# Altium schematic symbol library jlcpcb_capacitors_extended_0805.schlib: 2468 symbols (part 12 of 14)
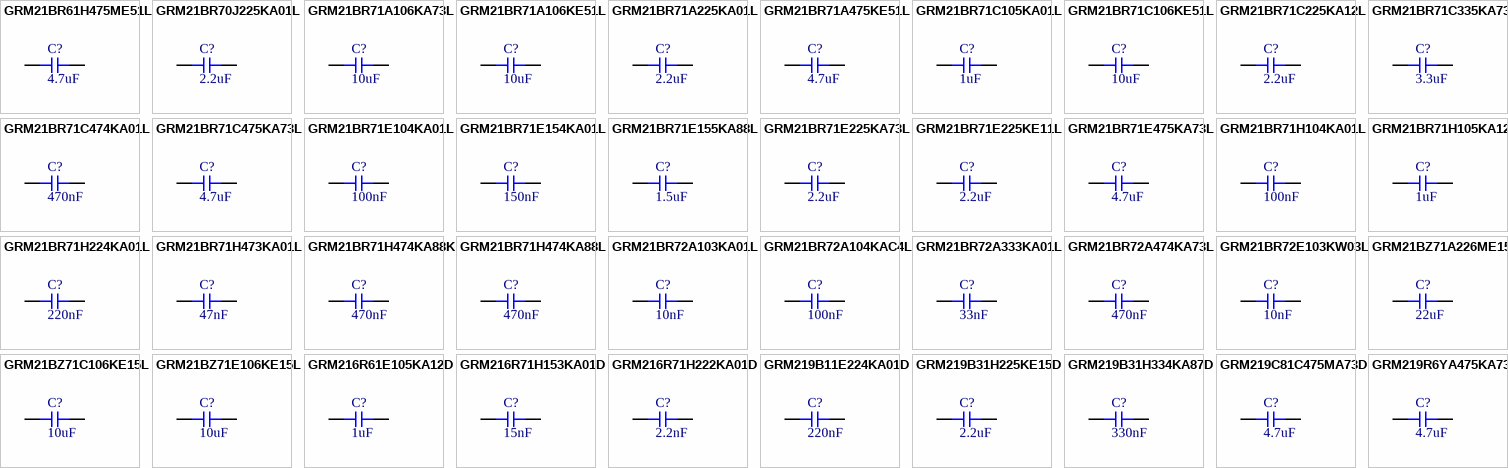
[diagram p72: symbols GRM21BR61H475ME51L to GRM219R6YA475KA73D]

## GRM21BR71C225KA12L
designator C?  Capacitance: 2.2uF  (hidden comment: *)
Capacitor, Ceramic (MLCC), 2.2uF, ±10%, 16V, X7R, ±10%, SMD 0805; Manufacturer: Murata Electronics; Manufacturer Part Number: GRM21BR71C225KA12L
footprint CAP-0805 (0805 (2012M) Capacitor)
pins: 1, 2

## GRM21BR71C335KA73L
designator C?  Capacitance: 3.3uF  (hidden comment: *)
Capacitor, Ceramic (MLCC), 3.3uF, ±10%, 16V, X7R, ±10%, SMD 0805; Manufacturer: Murata Electronics; Manufacturer Part Number: GRM21BR71C335KA73L
footprint CAP-0805 (0805 (2012M) Capacitor)
pins: 1, 2

## GRM21BR71C474KA01L
designator C?  Capacitance: 470nF  (hidden comment: *)
Capacitor, Ceramic (MLCC), 470nF, ±10%, 16V, X7R, ±10%, SMD 0805; Manufacturer: Murata Electronics; Manufacturer Part Number: GRM21BR71C474KA01L
footprint CAP-0805 (0805 (2012M) Capacitor)
pins: 1, 2

## GRM21BR71C475KA73L
designator C?  Capacitance: 4.7uF  (hidden comment: *)
Capacitor, Ceramic (MLCC), 4.7uF, ±10%, 16V, X7R, ±10%, SMD 0805; Manufacturer: Murata Electronics; Manufacturer Part Number: GRM21BR71C475KA73L
footprint CAP-0805 (0805 (2012M) Capacitor)
pins: 1, 2

## GRM21BR71E104KA01L
designator C?  Capacitance: 100nF  (hidden comment: *)
Capacitor, Ceramic (MLCC), 100nF, ±10%, 25V, X7R, ±10%, SMD 0805; Manufacturer: Murata Electronics; Manufacturer Part Number: GRM21BR71E104KA01L
footprint CAP-0805 (0805 (2012M) Capacitor)
pins: 1, 2

## GRM21BR71E154KA01L
designator C?  Capacitance: 150nF  (hidden comment: *)
Capacitor, Ceramic (MLCC), 150nF, ±10%, 25V, X7R, ±10%, SMD 0805; Manufacturer: Murata Electronics; Manufacturer Part Number: GRM21BR71E154KA01L
footprint CAP-0805 (0805 (2012M) Capacitor)
pins: 1, 2

## GRM21BR71E155KA88L
designator C?  Capacitance: 1.5uF  (hidden comment: *)
Capacitor, Ceramic (MLCC), 1.5uF, ±10%, 25V, X7R, ±10%, SMD 0805; Manufacturer: Murata Electronics; Manufacturer Part Number: GRM21BR71E155KA88L
footprint CAP-0805 (0805 (2012M) Capacitor)
pins: 1, 2

## GRM21BR71E225KA73L
designator C?  Capacitance: 2.2uF  (hidden comment: *)
Capacitor, Ceramic (MLCC), 2.2uF, ±10%, 25V, X7R, ±10%, SMD 0805; Manufacturer: Murata Electronics; Manufacturer Part Number: GRM21BR71E225KA73L
footprint CAP-0805 (0805 (2012M) Capacitor)
pins: 1, 2

## GRM21BR71E225KE11L
designator C?  Capacitance: 2.2uF  (hidden comment: *)
Capacitor, Ceramic (MLCC), 2.2uF, ±10%, 25V, X7R, ±10%, SMD 0805; Manufacturer: Murata Electronics; Manufacturer Part Number: GRM21BR71E225KE11L
footprint CAP-0805 (0805 (2012M) Capacitor)
pins: 1, 2

## GRM21BR71E475KA73L
designator C?  Capacitance: 4.7uF  (hidden comment: *)
Capacitor, Ceramic (MLCC), 4.7uF, ±10%, 25V, X7R, ±10%, SMD 0805; Manufacturer: Murata Electronics; Manufacturer Part Number: GRM21BR71E475KA73L
footprint CAP-0805 (0805 (2012M) Capacitor)
pins: 1, 2

## GRM21BR71H104KA01L
designator C?  Capacitance: 100nF  (hidden comment: *)
Capacitor, Ceramic (MLCC), 100nF, ±10%, 50V, X7R, ±10%, SMD 0805; Manufacturer: Murata Electronics; Manufacturer Part Number: GRM21BR71H104KA01L
footprint CAP-0805 (0805 (2012M) Capacitor)
pins: 1, 2

## GRM21BR71H105KA12L
designator C?  Capacitance: 1uF  (hidden comment: *)
Capacitor, Ceramic (MLCC), 1uF, ±10%, 50V, X7R, ±10%, SMD 0805; Manufacturer: Murata Electronics; Manufacturer Part Number: GRM21BR71H105KA12L
footprint CAP-0805 (0805 (2012M) Capacitor)
pins: 1, 2

## GRM21BR71H224KA01L
designator C?  Capacitance: 220nF  (hidden comment: *)
Capacitor, Ceramic (MLCC), 220nF, ±10%, 50V, X7R, ±10%, SMD 0805; Manufacturer: Murata Electronics; Manufacturer Part Number: GRM21BR71H224KA01L
footprint CAP-0805 (0805 (2012M) Capacitor)
pins: 1, 2

## GRM21BR71H473KA01L
designator C?  Capacitance: 47nF  (hidden comment: *)
Capacitor, Ceramic (MLCC), 47nF, ±10%, 50V, X7R, ±10%, SMD 0805; Manufacturer: Murata Electronics; Manufacturer Part Number: GRM21BR71H473KA01L
footprint CAP-0805 (0805 (2012M) Capacitor)
pins: 1, 2

## GRM21BR71H474KA88K
designator C?  Capacitance: 470nF  (hidden comment: *)
Capacitor, Ceramic (MLCC), 470nF, ±10%, 50V, X7R, ±10%, SMD 0805; Manufacturer: Murata Electronics; Manufacturer Part Number: GRM21BR71H474KA88K
footprint CAP-0805 (0805 (2012M) Capacitor)
pins: 1, 2

## GRM21BR71H474KA88L
designator C?  Capacitance: 470nF  (hidden comment: *)
Capacitor, Ceramic (MLCC), 470nF, ±10%, 50V, X7R, ±10%, SMD 0805; Manufacturer: Murata Electronics; Manufacturer Part Number: GRM21BR71H474KA88L
footprint CAP-0805 (0805 (2012M) Capacitor)
pins: 1, 2

## GRM21BR72A103KA01L
designator C?  Capacitance: 10nF  (hidden comment: *)
Capacitor, Ceramic (MLCC), 10nF, ±10%, 100V, X7R, ±10%, SMD 0805; Manufacturer: Murata Electronics; Manufacturer Part Number: GRM21BR72A103KA01L
footprint CAP-0805 (0805 (2012M) Capacitor)
pins: 1, 2

## GRM21BR72A104KAC4L
designator C?  Capacitance: 100nF  (hidden comment: *)
Capacitor, Ceramic (MLCC), 100nF, ±10%, 100V, X7R, ±10%, SMD 0805; Manufacturer: Murata Electronics; Manufacturer Part Number: GRM21BR72A104KAC4L
footprint CAP-0805 (0805 (2012M) Capacitor)
pins: 1, 2

## GRM21BR72A333KA01L
designator C?  Capacitance: 33nF  (hidden comment: *)
Capacitor, Ceramic (MLCC), 33nF, ±10%, 100V, X7R, ±10%, SMD 0805; Manufacturer: Murata Electronics; Manufacturer Part Number: GRM21BR72A333KA01L
footprint CAP-0805 (0805 (2012M) Capacitor)
pins: 1, 2

## GRM21BR72A474KA73L
designator C?  Capacitance: 470nF  (hidden comment: *)
Capacitor, Ceramic (MLCC), 470nF, ±10%, 100V, X7R, ±10%, SMD 0805; Manufacturer: Murata Electronics; Manufacturer Part Number: GRM21BR72A474KA73L
footprint CAP-0805 (0805 (2012M) Capacitor)
pins: 1, 2

## GRM21BR72E103KW03L
designator C?  Capacitance: 10nF  (hidden comment: *)
Capacitor, Ceramic (MLCC), 10nF, ±10%, 250V, X7R, ±10%, SMD 0805; Manufacturer: Murata Electronics; Manufacturer Part Number: GRM21BR72E103KW03L
footprint CAP-0805 (0805 (2012M) Capacitor)
pins: 1, 2

## GRM21BZ71A226ME15L
designator C?  Capacitance: 22uF  (hidden comment: *)
Capacitor, Ceramic (MLCC), 22uF, ±20%, ±20%, SMD 0805; Manufacturer: Murata Electronics; Manufacturer Part Number: GRM21BZ71A226ME15L
footprint CAP-0805 (0805 (2012M) Capacitor)
pins: 1, 2

## GRM21BZ71C106KE15L
designator C?  Capacitance: 10uF  (hidden comment: *)
Capacitor, Ceramic (MLCC), 10uF, ±10%, 16V, X7R, ±10%, SMD 0805; Manufacturer: Murata Electronics; Manufacturer Part Number: GRM21BZ71C106KE15L
footprint CAP-0805 (0805 (2012M) Capacitor)
pins: 1, 2

## GRM21BZ71E106KE15L
designator C?  Capacitance: 10uF  (hidden comment: *)
Capacitor, Ceramic (MLCC), 10uF, ±10%, 25V, X7R, ±10%, SMD 0805; Manufacturer: Murata Electronics; Manufacturer Part Number: GRM21BZ71E106KE15L
footprint CAP-0805 (0805 (2012M) Capacitor)
pins: 1, 2

## GRM216R61E105KA12D
designator C?  Capacitance: 1uF  (hidden comment: *)
Capacitor, Ceramic (MLCC), 1uF, ±10%, ±10%, SMD 0805; Manufacturer: Murata Electronics; Manufacturer Part Number: GRM216R61E105KA12D
footprint CAP-0805 (0805 (2012M) Capacitor)
pins: 1, 2

## GRM216R71H153KA01D
designator C?  Capacitance: 15nF  (hidden comment: *)
Capacitor, Ceramic (MLCC), 15nF, ±10%, 50V, X7R, ±10%, SMD 0805; Manufacturer: Murata Electronics; Manufacturer Part Number: GRM216R71H153KA01D
footprint CAP-0805 (0805 (2012M) Capacitor)
pins: 1, 2

## GRM216R71H222KA01D
designator C?  Capacitance: 2.2nF  (hidden comment: *)
Capacitor, Ceramic (MLCC), 2.2nF, ±10%, 50V, X7R, ±10%, SMD 0805; Manufacturer: Murata Electronics; Manufacturer Part Number: GRM216R71H222KA01D
footprint CAP-0805 (0805 (2012M) Capacitor)
pins: 1, 2

## GRM219B11E224KA01D
designator C?  Capacitance: 220nF  (hidden comment: *)
Capacitor, Ceramic (MLCC), 220nF, ±10%, 25V, B, ±10%, SMD 0805; Manufacturer: Murata Electronics; Manufacturer Part Number: GRM219B11E224KA01D
footprint CAP-0805 (0805 (2012M) Capacitor)
pins: 1, 2

## GRM219B31H225KE15D
designator C?  Capacitance: 2.2uF  (hidden comment: *)
Capacitor, Ceramic (MLCC), 2.2uF, ±10%, 50V, B, ±10%, SMD 0805; Manufacturer: Murata Electronics; Manufacturer Part Number: GRM219B31H225KE15D
footprint CAP-0805 (0805 (2012M) Capacitor)
pins: 1, 2

## GRM219B31H334KA87D
designator C?  Capacitance: 330nF  (hidden comment: *)
Capacitor, Ceramic (MLCC), 330nF, ±10%, 50V, B, ±10%, SMD 0805; Manufacturer: Murata Electronics; Manufacturer Part Number: GRM219B31H334KA87D
footprint CAP-0805 (0805 (2012M) Capacitor)
pins: 1, 2

## GRM219C81C475MA73D
designator C?  Capacitance: 4.7uF  (hidden comment: *)
Capacitor, Ceramic (MLCC), 4.7uF, ±20%, 16V, X6S, ±20%, SMD 0805; Manufacturer: Murata Electronics; Manufacturer Part Number: GRM219C81C475MA73D
footprint CAP-0805 (0805 (2012M) Capacitor)
pins: 1, 2

## GRM219R6YA475KA73D
designator C?  Capacitance: 4.7uF  (hidden comment: *)
Capacitor, Ceramic (MLCC), 4.7uF, ±10%, ±10%, SMD 0805; Manufacturer: Murata Electronics; Manufacturer Part Number: GRM219R6YA475KA73D
footprint CAP-0805 (0805 (2012M) Capacitor)
pins: 1, 2

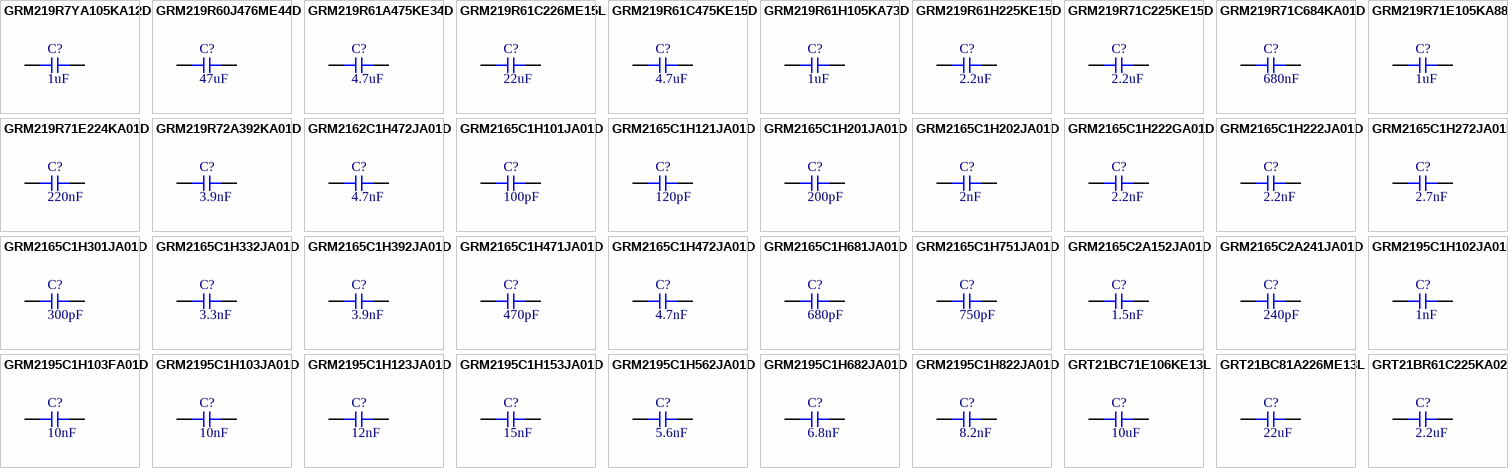
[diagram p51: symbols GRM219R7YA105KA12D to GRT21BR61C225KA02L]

## GRM219R7YA105KA12D
designator C?  Capacitance: 1uF  (hidden comment: *)
Capacitor, Ceramic (MLCC), 1uF, ±10%, 35V, X7R, ±10%, SMD 0805; Manufacturer: Murata Electronics; Manufacturer Part Number: GRM219R7YA105KA12D
footprint CAP-0805 (0805 (2012M) Capacitor)
pins: 1, 2

## GRM219R60J476ME44D
designator C?  Capacitance: 47uF  (hidden comment: *)
Capacitor, Ceramic (MLCC), 47uF, ±20%, 6.3V, X5R, ±20%, SMD 0805; Manufacturer: Murata Electronics; Manufacturer Part Number: GRM219R60J476ME44D
footprint CAP-0805 (0805 (2012M) Capacitor)
pins: 1, 2

## GRM219R61A475KE34D
designator C?  Capacitance: 4.7uF  (hidden comment: *)
Capacitor, Ceramic (MLCC), 4.7uF, ±10%, 10V, X5R, ±10%, SMD 0805; Manufacturer: Murata Electronics; Manufacturer Part Number: GRM219R61A475KE34D
footprint CAP-0805 (0805 (2012M) Capacitor)
pins: 1, 2

## GRM219R61C226ME15L
designator C?  Capacitance: 22uF  (hidden comment: *)
Capacitor, Ceramic (MLCC), 22uF, ±20%, 16V, X5R, ±20%, SMD 0805; Manufacturer: Murata Electronics; Manufacturer Part Number: GRM219R61C226ME15L
footprint CAP-0805 (0805 (2012M) Capacitor)
pins: 1, 2

## GRM219R61C475KE15D
designator C?  Capacitance: 4.7uF  (hidden comment: *)
Capacitor, Ceramic (MLCC), 4.7uF, ±10%, 16V, X5R, ±10%, SMD 0805; Manufacturer: Murata Electronics; Manufacturer Part Number: GRM219R61C475KE15D
footprint CAP-0805 (0805 (2012M) Capacitor)
pins: 1, 2

## GRM219R61H105KA73D
designator C?  Capacitance: 1uF  (hidden comment: *)
Capacitor, Ceramic (MLCC), 1uF, ±10%, 50V, X5R, ±10%, SMD 0805; Manufacturer: Murata Electronics; Manufacturer Part Number: GRM219R61H105KA73D
footprint CAP-0805 (0805 (2012M) Capacitor)
pins: 1, 2

## GRM219R61H225KE15D
designator C?  Capacitance: 2.2uF  (hidden comment: *)
Capacitor, Ceramic (MLCC), 2.2uF, ±10%, 50V, X5R, ±10%, SMD 0805; Manufacturer: Murata Electronics; Manufacturer Part Number: GRM219R61H225KE15D
footprint CAP-0805 (0805 (2012M) Capacitor)
pins: 1, 2

## GRM219R71C225KE15D
designator C?  Capacitance: 2.2uF  (hidden comment: *)
Capacitor, Ceramic (MLCC), 2.2uF, ±10%, 16V, X7R, ±10%, SMD 0805; Manufacturer: Murata Electronics; Manufacturer Part Number: GRM219R71C225KE15D
footprint CAP-0805 (0805 (2012M) Capacitor)
pins: 1, 2

## GRM219R71C684KA01D
designator C?  Capacitance: 680nF  (hidden comment: *)
Capacitor, Ceramic (MLCC), 680nF, ±10%, 16V, X7R, ±10%, SMD 0805; Manufacturer: Murata Electronics; Manufacturer Part Number: GRM219R71C684KA01D
footprint CAP-0805 (0805 (2012M) Capacitor)
pins: 1, 2

## GRM219R71E105KA88D
designator C?  Capacitance: 1uF  (hidden comment: *)
Capacitor, Ceramic (MLCC), 1uF, ±10%, 25V, X7R, ±10%, SMD 0805; Manufacturer: Murata Electronics; Manufacturer Part Number: GRM219R71E105KA88D
footprint CAP-0805 (0805 (2012M) Capacitor)
pins: 1, 2

## GRM219R71E224KA01D
designator C?  Capacitance: 220nF  (hidden comment: *)
Capacitor, Ceramic (MLCC), 220nF, ±10%, 25V, X7R, ±10%, SMD 0805; Manufacturer: Murata Electronics; Manufacturer Part Number: GRM219R71E224KA01D
footprint CAP-0805 (0805 (2012M) Capacitor)
pins: 1, 2

## GRM219R72A392KA01D
designator C?  Capacitance: 3.9nF  (hidden comment: *)
Capacitor, Ceramic (MLCC), 3.9nF, ±10%, 100V, X7R, ±10%, SMD 0805; Manufacturer: Murata Electronics; Manufacturer Part Number: GRM219R72A392KA01D
footprint CAP-0805 (0805 (2012M) Capacitor)
pins: 1, 2

## GRM2162C1H472JA01D
designator C?  Capacitance: 4.7nF  (hidden comment: *)
Capacitor, Ceramic (MLCC), 4.7nF, ±5%, 50V, CH, ±5%, SMD 0805; Manufacturer: Murata Electronics; Manufacturer Part Number: GRM2162C1H472JA01D
footprint CAP-0805 (0805 (2012M) Capacitor)
pins: 1, 2

## GRM2165C1H101JA01D
designator C?  Capacitance: 100pF  (hidden comment: *)
Capacitor, Ceramic (MLCC), 100pF, ±5%, 50V, C0G, ±5%, SMD 0805; Manufacturer: Murata Electronics; Manufacturer Part Number: GRM2165C1H101JA01D
footprint CAP-0805 (0805 (2012M) Capacitor)
pins: 1, 2

## GRM2165C1H121JA01D
designator C?  Capacitance: 120pF  (hidden comment: *)
Capacitor, Ceramic (MLCC), 120pF, ±5%, 50V, C0G, ±5%, SMD 0805; Manufacturer: Murata Electronics; Manufacturer Part Number: GRM2165C1H121JA01D
footprint CAP-0805 (0805 (2012M) Capacitor)
pins: 1, 2

## GRM2165C1H201JA01D
designator C?  Capacitance: 200pF  (hidden comment: *)
Capacitor, Ceramic (MLCC), 200pF, ±5%, 50V, C0G, ±5%, SMD 0805; Manufacturer: Murata Electronics; Manufacturer Part Number: GRM2165C1H201JA01D
footprint CAP-0805 (0805 (2012M) Capacitor)
pins: 1, 2

## GRM2165C1H202JA01D
designator C?  Capacitance: 2nF  (hidden comment: *)
Capacitor, Ceramic (MLCC), 2nF, ±5%, 50V, C0G, ±5%, SMD 0805; Manufacturer: Murata Electronics; Manufacturer Part Number: GRM2165C1H202JA01D
footprint CAP-0805 (0805 (2012M) Capacitor)
pins: 1, 2

## GRM2165C1H222GA01D
designator C?  Capacitance: 2.2nF  (hidden comment: *)
Capacitor, Ceramic (MLCC), 2.2nF, ±2%, 50V, C0G, ±2%, SMD 0805; Manufacturer: Murata Electronics; Manufacturer Part Number: GRM2165C1H222GA01D
footprint CAP-0805 (0805 (2012M) Capacitor)
pins: 1, 2

## GRM2165C1H222JA01D
designator C?  Capacitance: 2.2nF  (hidden comment: *)
Capacitor, Ceramic (MLCC), 2.2nF, ±5%, 50V, C0G, ±5%, SMD 0805; Manufacturer: Murata Electronics; Manufacturer Part Number: GRM2165C1H222JA01D
footprint CAP-0805 (0805 (2012M) Capacitor)
pins: 1, 2

## GRM2165C1H272JA01D
designator C?  Capacitance: 2.7nF  (hidden comment: *)
Capacitor, Ceramic (MLCC), 2.7nF, ±5%, 50V, C0G, ±5%, SMD 0805; Manufacturer: Murata Electronics; Manufacturer Part Number: GRM2165C1H272JA01D
footprint CAP-0805 (0805 (2012M) Capacitor)
pins: 1, 2

## GRM2165C1H301JA01D
designator C?  Capacitance: 300pF  (hidden comment: *)
Capacitor, Ceramic (MLCC), 300pF, ±5%, 50V, C0G, ±5%, SMD 0805; Manufacturer: Murata Electronics; Manufacturer Part Number: GRM2165C1H301JA01D
footprint CAP-0805 (0805 (2012M) Capacitor)
pins: 1, 2

## GRM2165C1H332JA01D
designator C?  Capacitance: 3.3nF  (hidden comment: *)
Capacitor, Ceramic (MLCC), 3.3nF, ±5%, 50V, C0G, ±5%, SMD 0805; Manufacturer: Murata Electronics; Manufacturer Part Number: GRM2165C1H332JA01D
footprint CAP-0805 (0805 (2012M) Capacitor)
pins: 1, 2

## GRM2165C1H392JA01D
designator C?  Capacitance: 3.9nF  (hidden comment: *)
Capacitor, Ceramic (MLCC), 3.9nF, ±5%, 50V, C0G, ±5%, SMD 0805; Manufacturer: Murata Electronics; Manufacturer Part Number: GRM2165C1H392JA01D
footprint CAP-0805 (0805 (2012M) Capacitor)
pins: 1, 2

## GRM2165C1H471JA01D
designator C?  Capacitance: 470pF  (hidden comment: *)
Capacitor, Ceramic (MLCC), 470pF, ±5%, 50V, C0G, ±5%, SMD 0805; Manufacturer: Murata Electronics; Manufacturer Part Number: GRM2165C1H471JA01D
footprint CAP-0805 (0805 (2012M) Capacitor)
pins: 1, 2

## GRM2165C1H472JA01D
designator C?  Capacitance: 4.7nF  (hidden comment: *)
Capacitor, Ceramic (MLCC), 4.7nF, ±5%, 50V, C0G, ±5%, SMD 0805; Manufacturer: Murata Electronics; Manufacturer Part Number: GRM2165C1H472JA01D
footprint CAP-0805 (0805 (2012M) Capacitor)
pins: 1, 2

## GRM2165C1H681JA01D
designator C?  Capacitance: 680pF  (hidden comment: *)
Capacitor, Ceramic (MLCC), 680pF, ±5%, 50V, C0G, ±5%, SMD 0805; Manufacturer: Murata Electronics; Manufacturer Part Number: GRM2165C1H681JA01D
footprint CAP-0805 (0805 (2012M) Capacitor)
pins: 1, 2

## GRM2165C1H751JA01D
designator C?  Capacitance: 750pF  (hidden comment: *)
Capacitor, Ceramic (MLCC), 750pF, ±5%, 50V, C0G, ±5%, SMD 0805; Manufacturer: Murata Electronics; Manufacturer Part Number: GRM2165C1H751JA01D
footprint CAP-0805 (0805 (2012M) Capacitor)
pins: 1, 2

## GRM2165C2A152JA01D
designator C?  Capacitance: 1.5nF  (hidden comment: *)
Capacitor, Ceramic (MLCC), 1.5nF, ±5%, 100V, C0G, ±5%, SMD 0805; Manufacturer: Murata Electronics; Manufacturer Part Number: GRM2165C2A152JA01D
footprint CAP-0805 (0805 (2012M) Capacitor)
pins: 1, 2

## GRM2165C2A241JA01D
designator C?  Capacitance: 240pF  (hidden comment: *)
Capacitor, Ceramic (MLCC), 240pF, ±5%, 100V, C0G, ±5%, SMD 0805; Manufacturer: Murata Electronics; Manufacturer Part Number: GRM2165C2A241JA01D
footprint CAP-0805 (0805 (2012M) Capacitor)
pins: 1, 2

## GRM2195C1H102JA01D
designator C?  Capacitance: 1nF  (hidden comment: *)
Capacitor, Ceramic (MLCC), 1nF, ±5%, 50V, C0G, ±5%, SMD 0805; Manufacturer: Murata Electronics; Manufacturer Part Number: GRM2195C1H102JA01D
footprint CAP-0805 (0805 (2012M) Capacitor)
pins: 1, 2

## GRM2195C1H103FA01D
designator C?  Capacitance: 10nF  (hidden comment: *)
Capacitor, Ceramic (MLCC), 10nF, ±1%, 50V, C0G, ±1%, SMD 0805; Manufacturer: Murata Electronics; Manufacturer Part Number: GRM2195C1H103FA01D
footprint CAP-0805 (0805 (2012M) Capacitor)
pins: 1, 2

## GRM2195C1H103JA01D
designator C?  Capacitance: 10nF  (hidden comment: *)
Capacitor, Ceramic (MLCC), 10nF, ±5%, 50V, C0G, ±5%, SMD 0805; Manufacturer: Murata Electronics; Manufacturer Part Number: GRM2195C1H103JA01D
footprint CAP-0805 (0805 (2012M) Capacitor)
pins: 1, 2

## GRM2195C1H123JA01D
designator C?  Capacitance: 12nF  (hidden comment: *)
Capacitor, Ceramic (MLCC), 12nF, ±5%, 50V, C0G, ±5%, SMD 0805; Manufacturer: Murata Electronics; Manufacturer Part Number: GRM2195C1H123JA01D
footprint CAP-0805 (0805 (2012M) Capacitor)
pins: 1, 2

## GRM2195C1H153JA01D
designator C?  Capacitance: 15nF  (hidden comment: *)
Capacitor, Ceramic (MLCC), 15nF, ±5%, 50V, C0G, ±5%, SMD 0805; Manufacturer: Murata Electronics; Manufacturer Part Number: GRM2195C1H153JA01D
footprint CAP-0805 (0805 (2012M) Capacitor)
pins: 1, 2

## GRM2195C1H562JA01D
designator C?  Capacitance: 5.6nF  (hidden comment: *)
Capacitor, Ceramic (MLCC), 5.6nF, ±5%, 50V, C0G, ±5%, SMD 0805; Manufacturer: Murata Electronics; Manufacturer Part Number: GRM2195C1H562JA01D
footprint CAP-0805 (0805 (2012M) Capacitor)
pins: 1, 2

## GRM2195C1H682JA01D
designator C?  Capacitance: 6.8nF  (hidden comment: *)
Capacitor, Ceramic (MLCC), 6.8nF, ±5%, 50V, C0G, ±5%, SMD 0805; Manufacturer: Murata Electronics; Manufacturer Part Number: GRM2195C1H682JA01D
footprint CAP-0805 (0805 (2012M) Capacitor)
pins: 1, 2

## GRM2195C1H822JA01D
designator C?  Capacitance: 8.2nF  (hidden comment: *)
Capacitor, Ceramic (MLCC), 8.2nF, ±5%, 50V, C0G, ±5%, SMD 0805; Manufacturer: Murata Electronics; Manufacturer Part Number: GRM2195C1H822JA01D
footprint CAP-0805 (0805 (2012M) Capacitor)
pins: 1, 2

## GRT21BC71E106KE13L
designator C?  Capacitance: 10uF  (hidden comment: *)
Capacitor, Ceramic (MLCC), 10uF, ±10%, ±10%, SMD 0805; Manufacturer: Murata Electronics; Manufacturer Part Number: GRT21BC71E106KE13L
footprint CAP-0805 (0805 (2012M) Capacitor)
pins: 1, 2

## GRT21BC81A226ME13L
designator C?  Capacitance: 22uF  (hidden comment: *)
Capacitor, Ceramic (MLCC), 22uF, ±20%, 10V, X6S, ±20%, SMD 0805; Manufacturer: Murata Electronics; Manufacturer Part Number: GRT21BC81A226ME13L
footprint CAP-0805 (0805 (2012M) Capacitor)
pins: 1, 2

## GRT21BR61C225KA02L
designator C?  Capacitance: 2.2uF  (hidden comment: *)
Capacitor, Ceramic (MLCC), 2.2uF, ±10%, ±10%, SMD 0805; Manufacturer: Murata Electronics; Manufacturer Part Number: GRT21BR61C225KA02L
footprint CAP-0805 (0805 (2012M) Capacitor)
pins: 1, 2

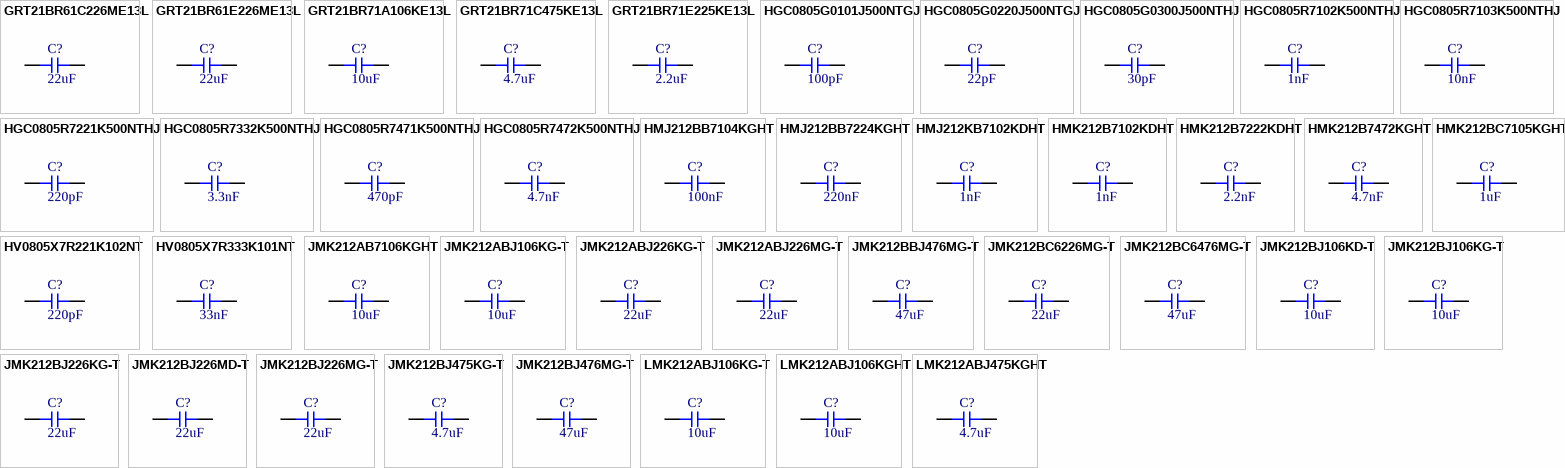
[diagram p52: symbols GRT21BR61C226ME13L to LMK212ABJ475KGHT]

## GRT21BR61C226ME13L
designator C?  Capacitance: 22uF  (hidden comment: *)
Capacitor, Ceramic (MLCC), 22uF, ±20%, ±20%, SMD 0805; Manufacturer: Murata Electronics; Manufacturer Part Number: GRT21BR61C226ME13L
footprint CAP-0805 (0805 (2012M) Capacitor)
pins: 1, 2

## GRT21BR61E226ME13L
designator C?  Capacitance: 22uF  (hidden comment: *)
Capacitor, Ceramic (MLCC), 22uF, ±20%, 25V, X5R, ±20%, SMD 0805; Manufacturer: Murata Electronics; Manufacturer Part Number: GRT21BR61E226ME13L
footprint CAP-0805 (0805 (2012M) Capacitor)
pins: 1, 2

## GRT21BR71A106KE13L
designator C?  Capacitance: 10uF  (hidden comment: *)
Capacitor, Ceramic (MLCC), 10uF, ±10%, 10V, X7R, ±10%, SMD 0805; Manufacturer: Murata Electronics; Manufacturer Part Number: GRT21BR71A106KE13L
footprint CAP-0805 (0805 (2012M) Capacitor)
pins: 1, 2

## GRT21BR71C475KE13L
designator C?  Capacitance: 4.7uF  (hidden comment: *)
Capacitor, Ceramic (MLCC), 4.7uF, ±10%, 16V, X7R, ±10%, SMD 0805; Manufacturer: Murata Electronics; Manufacturer Part Number: GRT21BR71C475KE13L
footprint CAP-0805 (0805 (2012M) Capacitor)
pins: 1, 2

## GRT21BR71E225KE13L
designator C?  Capacitance: 2.2uF  (hidden comment: *)
Capacitor, Ceramic (MLCC), 2.2uF, ±10%, 25V, X7R, ±10%, SMD 0805; Manufacturer: Murata Electronics; Manufacturer Part Number: GRT21BR71E225KE13L
footprint CAP-0805 (0805 (2012M) Capacitor)
pins: 1, 2

## HGC0805G0101J500NTGJ
designator C?  Capacitance: 100pF  (hidden comment: *)
Capacitor, Ceramic (MLCC), 100pF, ±5%, 50V, C0G, ±5%, SMD 0805; Manufacturer: Chinocera; Manufacturer Part Number: HGC0805G0101J500NTGJ
footprint CAP-0805 (0805 (2012M) Capacitor)
pins: 1, 2

## HGC0805G0220J500NTGJ
designator C?  Capacitance: 22pF  (hidden comment: *)
Capacitor, Ceramic (MLCC), 22pF, ±5%, 50V, C0G, ±5%, SMD 0805; Manufacturer: Chinocera; Manufacturer Part Number: HGC0805G0220J500NTGJ
footprint CAP-0805 (0805 (2012M) Capacitor)
pins: 1, 2

## HGC0805G0300J500NTHJ
designator C?  Capacitance: 30pF  (hidden comment: *)
Capacitor, Ceramic (MLCC), 30pF, ±5%, 50V, C0G, ±5%, SMD 0805; Manufacturer: Chinocera; Manufacturer Part Number: HGC0805G0300J500NTHJ
footprint CAP-0805 (0805 (2012M) Capacitor)
pins: 1, 2

## HGC0805R7102K500NTHJ
designator C?  Capacitance: 1nF  (hidden comment: *)
Capacitor, Ceramic (MLCC), 1nF, ±10%, 50V, X7R, ±10%, SMD 0805; Manufacturer: Chinocera; Manufacturer Part Number: HGC0805R7102K500NTHJ
footprint CAP-0805 (0805 (2012M) Capacitor)
pins: 1, 2

## HGC0805R7103K500NTHJ
designator C?  Capacitance: 10nF  (hidden comment: *)
Capacitor, Ceramic (MLCC), 10nF, ±10%, 50V, X7R, ±10%, SMD 0805; Manufacturer: Chinocera; Manufacturer Part Number: HGC0805R7103K500NTHJ
footprint CAP-0805 (0805 (2012M) Capacitor)
pins: 1, 2

## HGC0805R7221K500NTHJ
designator C?  Capacitance: 220pF  (hidden comment: *)
Capacitor, Ceramic (MLCC), 220pF, ±10%, 50V, X7R, ±10%, SMD 0805; Manufacturer: Chinocera; Manufacturer Part Number: HGC0805R7221K500NTHJ
footprint CAP-0805 (0805 (2012M) Capacitor)
pins: 1, 2

## HGC0805R7332K500NTHJ
designator C?  Capacitance: 3.3nF  (hidden comment: *)
Capacitor, Ceramic (MLCC), 3.3nF, ±10%, 50V, X7R, ±10%, SMD 0805; Manufacturer: Chinocera; Manufacturer Part Number: HGC0805R7332K500NTHJ
footprint CAP-0805 (0805 (2012M) Capacitor)
pins: 1, 2

## HGC0805R7471K500NTHJ
designator C?  Capacitance: 470pF  (hidden comment: *)
Capacitor, Ceramic (MLCC), 470pF, ±10%, 50V, X7R, ±10%, SMD 0805; Manufacturer: Chinocera; Manufacturer Part Number: HGC0805R7471K500NTHJ
footprint CAP-0805 (0805 (2012M) Capacitor)
pins: 1, 2

## HGC0805R7472K500NTHJ
designator C?  Capacitance: 4.7nF  (hidden comment: *)
Capacitor, Ceramic (MLCC), 4.7nF, ±10%, 50V, X7R, ±10%, SMD 0805; Manufacturer: Chinocera; Manufacturer Part Number: HGC0805R7472K500NTHJ
footprint CAP-0805 (0805 (2012M) Capacitor)
pins: 1, 2

## HMJ212BB7104KGHT
designator C?  Capacitance: 100nF  (hidden comment: *)
Capacitor, Ceramic (MLCC), 100nF, ±10%, 100V, X7R, ±10%, SMD 0805; Manufacturer: Taiyo Yuden; Manufacturer Part Number: HMJ212BB7104KGHT
footprint CAP-0805 (0805 (2012M) Capacitor)
pins: 1, 2

## HMJ212BB7224KGHT
designator C?  Capacitance: 220nF  (hidden comment: *)
Capacitor, Ceramic (MLCC), 220nF, ±10%, 100V, X7R, ±10%, SMD 0805; Manufacturer: Taiyo Yuden; Manufacturer Part Number: HMJ212BB7224KGHT
footprint CAP-0805 (0805 (2012M) Capacitor)
pins: 1, 2

## HMJ212KB7102KDHT
designator C?  Capacitance: 1nF  (hidden comment: *)
Capacitor, Ceramic (MLCC), 1nF, ±10%, 100V, ±10%, SMD 0805; Manufacturer: Taiyo Yuden; Manufacturer Part Number: HMJ212KB7102KDHT
footprint CAP-0805 (0805 (2012M) Capacitor)
pins: 1, 2

## HMK212B7102KDHT
designator C?  Capacitance: 1nF  (hidden comment: *)
Capacitor, Ceramic (MLCC), 1nF, ±10%, 100V, X7R, ±10%, SMD 0805; Manufacturer: Taiyo Yuden; Manufacturer Part Number: HMK212B7102KDHT
footprint CAP-0805 (0805 (2012M) Capacitor)
pins: 1, 2

## HMK212B7222KDHT
designator C?  Capacitance: 2.2nF  (hidden comment: *)
Capacitor, Ceramic (MLCC), 2.2nF, ±10%, 100V, X7R, ±10%, SMD 0805; Manufacturer: Taiyo Yuden; Manufacturer Part Number: HMK212B7222KDHT
footprint CAP-0805 (0805 (2012M) Capacitor)
pins: 1, 2

## HMK212B7472KGHT
designator C?  Capacitance: 4.7nF  (hidden comment: *)
Capacitor, Ceramic (MLCC), 4.7nF, ±10%, 100V, X7R, ±10%, SMD 0805; Manufacturer: Taiyo Yuden; Manufacturer Part Number: HMK212B7472KGHT
footprint CAP-0805 (0805 (2012M) Capacitor)
pins: 1, 2

## HMK212BC7105KGHTE
designator C?  Capacitance: 1uF  (hidden comment: *)
Capacitor, Ceramic (MLCC), 1uF, ±10%, 100V, ±10%, SMD 0805; Manufacturer: Taiyo Yuden; Manufacturer Part Number: HMK212BC7105KGHTE
footprint CAP-0805 (0805 (2012M) Capacitor)
pins: 1, 2

## HV0805X7R221K102NT
designator C?  Capacitance: 220pF  (hidden comment: *)
Capacitor, Ceramic (MLCC), 220pF, ±10%, 1kV, ±10%, SMD 0805; Manufacturer: AIDE; Manufacturer Part Number: HV0805X7R221K102NT
footprint CAP-0805 (0805 (2012M) Capacitor)
pins: 1, 2

## HV0805X7R333K101NT
designator C?  Capacitance: 33nF  (hidden comment: *)
Capacitor, Ceramic (MLCC), 33nF, ±10%, 100V, ±10%, SMD 0805; Manufacturer: AIDE; Manufacturer Part Number: HV0805X7R333K101NT
footprint CAP-0805 (0805 (2012M) Capacitor)
pins: 1, 2

## JMK212AB7106KGHT
designator C?  Capacitance: 10uF  (hidden comment: *)
Capacitor, Ceramic (MLCC), 10uF, ±10%, 6.3V, X7R, ±10%, SMD 0805; Manufacturer: Taiyo Yuden; Manufacturer Part Number: JMK212AB7106KGHT
footprint CAP-0805 (0805 (2012M) Capacitor)
pins: 1, 2

## JMK212ABJ106KG-T
designator C?  Capacitance: 10uF  (hidden comment: *)
Capacitor, Ceramic (MLCC), 10uF, ±10%, 6.3V, X5R, ±10%, SMD 0805; Manufacturer: Taiyo Yuden; Manufacturer Part Number: JMK212ABJ106KG-T
footprint CAP-0805 (0805 (2012M) Capacitor)
pins: 1, 2

## JMK212ABJ226KG-T
designator C?  Capacitance: 22uF  (hidden comment: *)
Capacitor, Ceramic (MLCC), 22uF, ±10%, 6.3V, X5R, ±10%, SMD 0805; Manufacturer: Taiyo Yuden; Manufacturer Part Number: JMK212ABJ226KG-T
footprint CAP-0805 (0805 (2012M) Capacitor)
pins: 1, 2

## JMK212ABJ226MG-T
designator C?  Capacitance: 22uF  (hidden comment: *)
Capacitor, Ceramic (MLCC), 22uF, ±20%, 6.3V, X5R, ±20%, SMD 0805; Manufacturer: Taiyo Yuden; Manufacturer Part Number: JMK212ABJ226MG-T
footprint CAP-0805 (0805 (2012M) Capacitor)
pins: 1, 2

## JMK212BBJ476MG-T
designator C?  Capacitance: 47uF  (hidden comment: *)
Capacitor, Ceramic (MLCC), 47uF, ±20%, 6.3V, X5R, ±20%, SMD 0805; Manufacturer: Taiyo Yuden; Manufacturer Part Number: JMK212BBJ476MG-T
footprint CAP-0805 (0805 (2012M) Capacitor)
pins: 1, 2

## JMK212BC6226MG-T
designator C?  Capacitance: 22uF  (hidden comment: *)
Capacitor, Ceramic (MLCC), 22uF, ±20%, 6.3V, X6S, ±20%, SMD 0805; Manufacturer: Taiyo Yuden; Manufacturer Part Number: JMK212BC6226MG-T
footprint CAP-0805 (0805 (2012M) Capacitor)
pins: 1, 2

## JMK212BC6476MG-T
designator C?  Capacitance: 47uF  (hidden comment: *)
Capacitor, Ceramic (MLCC), 47uF, ±20%, 6.3V, X6S, ±20%, SMD 0805; Manufacturer: Taiyo Yuden; Manufacturer Part Number: JMK212BC6476MG-T
footprint CAP-0805 (0805 (2012M) Capacitor)
pins: 1, 2

## JMK212BJ106KD-T
designator C?  Capacitance: 10uF  (hidden comment: *)
Capacitor, Ceramic (MLCC), 10uF, ±10%, 6.3V, X5R, ±10%, SMD 0805; Manufacturer: Taiyo Yuden; Manufacturer Part Number: JMK212BJ106KD-T
footprint CAP-0805 (0805 (2012M) Capacitor)
pins: 1, 2

## JMK212BJ106KG-T
designator C?  Capacitance: 10uF  (hidden comment: *)
Capacitor, Ceramic (MLCC), 10uF, ±10%, 6.3V, X5R, ±10%, SMD 0805; Manufacturer: Taiyo Yuden; Manufacturer Part Number: JMK212BJ106KG-T
footprint CAP-0805 (0805 (2012M) Capacitor)
pins: 1, 2

## JMK212BJ226KG-T
designator C?  Capacitance: 22uF  (hidden comment: *)
Capacitor, Ceramic (MLCC), 22uF, ±10%, 6.3V, X5R, ±10%, SMD 0805; Manufacturer: Taiyo Yuden; Manufacturer Part Number: JMK212BJ226KG-T
footprint CAP-0805 (0805 (2012M) Capacitor)
pins: 1, 2

## JMK212BJ226MD-T
designator C?  Capacitance: 22uF  (hidden comment: *)
Capacitor, Ceramic (MLCC), 22uF, ±20%, 6.3V, X5R, ±20%, SMD 0805; Manufacturer: Taiyo Yuden; Manufacturer Part Number: JMK212BJ226MD-T
footprint CAP-0805 (0805 (2012M) Capacitor)
pins: 1, 2

## JMK212BJ226MG-T
designator C?  Capacitance: 22uF  (hidden comment: *)
Capacitor, Ceramic (MLCC), 22uF, ±20%, 6.3V, X5R, ±20%, SMD 0805; Manufacturer: Taiyo Yuden; Manufacturer Part Number: JMK212BJ226MG-T
footprint CAP-0805 (0805 (2012M) Capacitor)
pins: 1, 2

## JMK212BJ475KG-T
designator C?  Capacitance: 4.7uF  (hidden comment: *)
Capacitor, Ceramic (MLCC), 4.7uF, ±10%, 6.3V, X5R, ±10%, SMD 0805; Manufacturer: Taiyo Yuden; Manufacturer Part Number: JMK212BJ475KG-T
footprint CAP-0805 (0805 (2012M) Capacitor)
pins: 1, 2

## JMK212BJ476MG-T
designator C?  Capacitance: 47uF  (hidden comment: *)
Capacitor, Ceramic (MLCC), 47uF, ±20%, 6.3V, X5R, ±20%, SMD 0805; Manufacturer: Taiyo Yuden; Manufacturer Part Number: JMK212BJ476MG-T
footprint CAP-0805 (0805 (2012M) Capacitor)
pins: 1, 2

## LMK212ABJ106KG-T
designator C?  Capacitance: 10uF  (hidden comment: *)
Capacitor, Ceramic (MLCC), 10uF, ±10%, 10V, X5R, ±10%, SMD 0805; Manufacturer: Taiyo Yuden; Manufacturer Part Number: LMK212ABJ106KG-T
footprint CAP-0805 (0805 (2012M) Capacitor)
pins: 1, 2

## LMK212ABJ106KGHT
designator C?  Capacitance: 10uF  (hidden comment: *)
Capacitor, Ceramic (MLCC), 10uF, ±10%, 10V, X5R, ±10%, SMD 0805; Manufacturer: Taiyo Yuden; Manufacturer Part Number: LMK212ABJ106KGHT
footprint CAP-0805 (0805 (2012M) Capacitor)
pins: 1, 2

## LMK212ABJ475KGHT
designator C?  Capacitance: 4.7uF  (hidden comment: *)
Capacitor, Ceramic (MLCC), 4.7uF, ±10%, 10V, X5R, ±10%, SMD 0805; Manufacturer: Taiyo Yuden; Manufacturer Part Number: LMK212ABJ475KGHT
footprint CAP-0805 (0805 (2012M) Capacitor)
pins: 1, 2

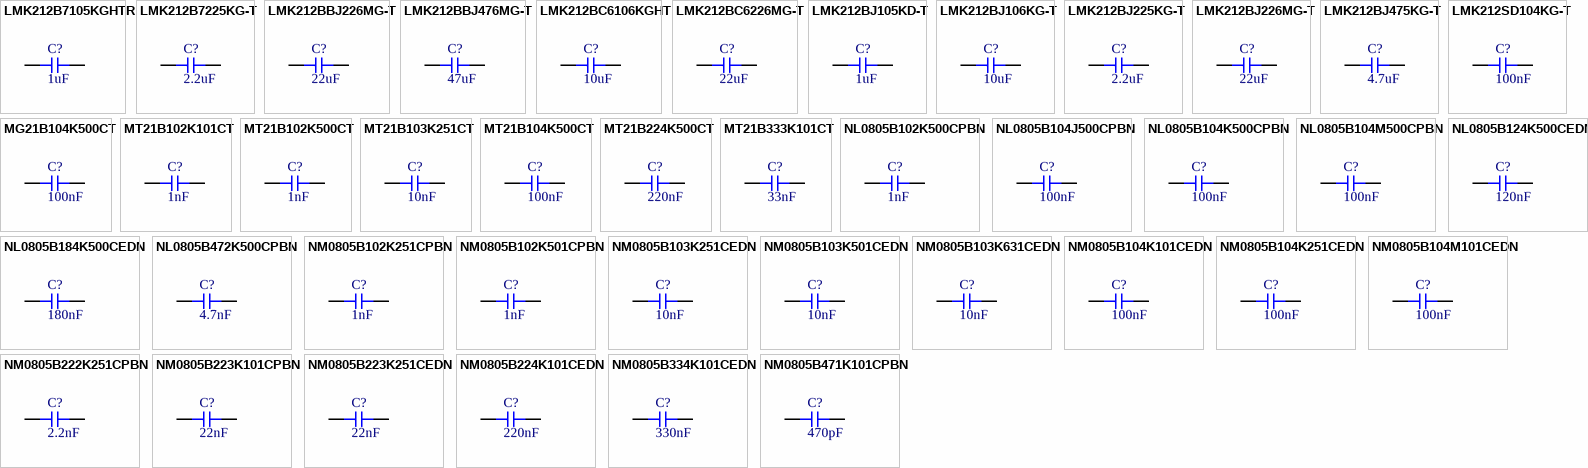
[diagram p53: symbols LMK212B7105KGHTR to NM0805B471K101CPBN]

## LMK212B7105KGHTR
designator C?  Capacitance: 1uF  (hidden comment: *)
Capacitor, Ceramic (MLCC), 1uF, ±10%, 10V, X7R, ±10%, SMD 0805; Manufacturer: Taiyo Yuden; Manufacturer Part Number: LMK212B7105KGHTR
footprint CAP-0805 (0805 (2012M) Capacitor)
pins: 1, 2

## LMK212B7225KG-T
designator C?  Capacitance: 2.2uF  (hidden comment: *)
Capacitor, Ceramic (MLCC), 2.2uF, ±10%, 10V, X7R, ±10%, SMD 0805; Manufacturer: Taiyo Yuden; Manufacturer Part Number: LMK212B7225KG-T
footprint CAP-0805 (0805 (2012M) Capacitor)
pins: 1, 2

## LMK212BBJ226MG-T
designator C?  Capacitance: 22uF  (hidden comment: *)
Capacitor, Ceramic (MLCC), 22uF, ±20%, 10V, X5R, ±20%, SMD 0805; Manufacturer: Taiyo Yuden; Manufacturer Part Number: LMK212BBJ226MG-T
footprint CAP-0805 (0805 (2012M) Capacitor)
pins: 1, 2

## LMK212BBJ476MG-T
designator C?  Capacitance: 47uF  (hidden comment: *)
Capacitor, Ceramic (MLCC), 47uF, ±20%, 10V, X5R, ±20%, SMD 0805; Manufacturer: Taiyo Yuden; Manufacturer Part Number: LMK212BBJ476MG-T
footprint CAP-0805 (0805 (2012M) Capacitor)
pins: 1, 2

## LMK212BC6106KGHT
designator C?  Capacitance: 10uF  (hidden comment: *)
Capacitor, Ceramic (MLCC), 10uF, ±10%, 10V, X6S, ±10%, SMD 0805; Manufacturer: Taiyo Yuden; Manufacturer Part Number: LMK212BC6106KGHT
footprint CAP-0805 (0805 (2012M) Capacitor)
pins: 1, 2

## LMK212BC6226MG-T
designator C?  Capacitance: 22uF  (hidden comment: *)
Capacitor, Ceramic (MLCC), 22uF, ±20%, 10V, X6S, ±20%, SMD 0805; Manufacturer: Taiyo Yuden; Manufacturer Part Number: LMK212BC6226MG-T
footprint CAP-0805 (0805 (2012M) Capacitor)
pins: 1, 2

## LMK212BJ105KD-T
designator C?  Capacitance: 1uF  (hidden comment: *)
Capacitor, Ceramic (MLCC), 1uF, ±10%, 10V, X5R, ±10%, SMD 0805; Manufacturer: Taiyo Yuden; Manufacturer Part Number: LMK212BJ105KD-T
footprint CAP-0805 (0805 (2012M) Capacitor)
pins: 1, 2

## LMK212BJ106KG-T
designator C?  Capacitance: 10uF  (hidden comment: *)
Capacitor, Ceramic (MLCC), 10uF, ±10%, 10V, X5R, ±10%, SMD 0805; Manufacturer: Taiyo Yuden; Manufacturer Part Number: LMK212BJ106KG-T
footprint CAP-0805 (0805 (2012M) Capacitor)
pins: 1, 2

## LMK212BJ225KG-T
designator C?  Capacitance: 2.2uF  (hidden comment: *)
Capacitor, Ceramic (MLCC), 2.2uF, ±10%, 10V, X5R, ±10%, SMD 0805; Manufacturer: Taiyo Yuden; Manufacturer Part Number: LMK212BJ225KG-T
footprint CAP-0805 (0805 (2012M) Capacitor)
pins: 1, 2

## LMK212BJ226MG-T
designator C?  Capacitance: 22uF  (hidden comment: *)
Capacitor, Ceramic (MLCC), 22uF, ±20%, 10V, X5R, ±20%, SMD 0805; Manufacturer: Taiyo Yuden; Manufacturer Part Number: LMK212BJ226MG-T
footprint CAP-0805 (0805 (2012M) Capacitor)
pins: 1, 2

## LMK212BJ475KG-T
designator C?  Capacitance: 4.7uF  (hidden comment: *)
Capacitor, Ceramic (MLCC), 4.7uF, ±10%, 10V, X5R, ±10%, SMD 0805; Manufacturer: Taiyo Yuden; Manufacturer Part Number: LMK212BJ475KG-T
footprint CAP-0805 (0805 (2012M) Capacitor)
pins: 1, 2

## LMK212SD104KG-T
designator C?  Capacitance: 100nF  (hidden comment: *)
Capacitor, Ceramic (MLCC), 100nF, ±10%, 10V, ±10%, SMD 0805; Manufacturer: Taiyo Yuden; Manufacturer Part Number: LMK212SD104KG-T
footprint CAP-0805 (0805 (2012M) Capacitor)
pins: 1, 2

## MG21B104K500CT
designator C?  Capacitance: 100nF  (hidden comment: *)
Capacitor, Ceramic (MLCC), 100nF, ±10%, 50V, X7R, ±10%, SMD 0805; Manufacturer: Walsin Tech Corp; Manufacturer Part Number: MG21B104K500CT
footprint CAP-0805 (0805 (2012M) Capacitor)
pins: 1, 2

## MT21B102K101CT
designator C?  Capacitance: 1nF  (hidden comment: *)
Capacitor, Ceramic (MLCC), 1nF, ±10%, 100V, X7R, ±10%, SMD 0805; Manufacturer: Walsin Tech Corp; Manufacturer Part Number: MT21B102K101CT
footprint CAP-0805 (0805 (2012M) Capacitor)
pins: 1, 2

## MT21B102K500CT
designator C?  Capacitance: 1nF  (hidden comment: *)
Capacitor, Ceramic (MLCC), 1nF, ±10%, 50V, X7R, ±10%, SMD 0805; Manufacturer: Walsin Tech Corp; Manufacturer Part Number: MT21B102K500CT
footprint CAP-0805 (0805 (2012M) Capacitor)
pins: 1, 2

## MT21B103K251CT
designator C?  Capacitance: 10nF  (hidden comment: *)
Capacitor, Ceramic (MLCC), 10nF, ±10%, 250V, X7R, ±10%, SMD 0805; Manufacturer: Walsin Tech Corp; Manufacturer Part Number: MT21B103K251CT
footprint CAP-0805 (0805 (2012M) Capacitor)
pins: 1, 2

## MT21B104K500CT
designator C?  Capacitance: 100nF  (hidden comment: *)
Capacitor, Ceramic (MLCC), 100nF, ±10%, 50V, X7R, ±10%, SMD 0805; Manufacturer: Walsin Tech Corp; Manufacturer Part Number: MT21B104K500CT
footprint CAP-0805 (0805 (2012M) Capacitor)
pins: 1, 2

## MT21B224K500CT
designator C?  Capacitance: 220nF  (hidden comment: *)
Capacitor, Ceramic (MLCC), 220nF, ±10%, 50V, X7R, ±10%, SMD 0805; Manufacturer: Walsin Tech Corp; Manufacturer Part Number: MT21B224K500CT
footprint CAP-0805 (0805 (2012M) Capacitor)
pins: 1, 2

## MT21B333K101CT
designator C?  Capacitance: 33nF  (hidden comment: *)
Capacitor, Ceramic (MLCC), 33nF, ±10%, 100V, X7R, ±10%, SMD 0805; Manufacturer: Walsin Tech Corp; Manufacturer Part Number: MT21B333K101CT
footprint CAP-0805 (0805 (2012M) Capacitor)
pins: 1, 2

## NL0805B102K500CPBN
designator C?  Capacitance: 1nF  (hidden comment: *)
Capacitor, Ceramic (MLCC), 1nF, ±10%, 50V, X7R, ±10%, SMD 0805; Manufacturer: HUI JU; Manufacturer Part Number: NL0805B102K500CPBN
footprint CAP-0805 (0805 (2012M) Capacitor)
pins: 1, 2

## NL0805B104J500CPBN
designator C?  Capacitance: 100nF  (hidden comment: *)
Capacitor, Ceramic (MLCC), 100nF, ±5%, 50V, X7R, ±5%, SMD 0805; Manufacturer: HUI JU; Manufacturer Part Number: NL0805B104J500CPBN
footprint CAP-0805 (0805 (2012M) Capacitor)
pins: 1, 2

## NL0805B104K500CPBN
designator C?  Capacitance: 100nF  (hidden comment: *)
Capacitor, Ceramic (MLCC), 100nF, ±10%, 50V, X7R, ±10%, SMD 0805; Manufacturer: HUI JU; Manufacturer Part Number: NL0805B104K500CPBN
footprint CAP-0805 (0805 (2012M) Capacitor)
pins: 1, 2

## NL0805B104M500CPBN
designator C?  Capacitance: 100nF  (hidden comment: *)
Capacitor, Ceramic (MLCC), 100nF, ±20%, 50V, X7R, ±20%, SMD 0805; Manufacturer: HUI JU; Manufacturer Part Number: NL0805B104M500CPBN
footprint CAP-0805 (0805 (2012M) Capacitor)
pins: 1, 2

## NL0805B124K500CEDN
designator C?  Capacitance: 120nF  (hidden comment: *)
Capacitor, Ceramic (MLCC), 120nF, ±10%, 50V, X7R, ±10%, SMD 0805; Manufacturer: HUI JU; Manufacturer Part Number: NL0805B124K500CEDN
footprint CAP-0805 (0805 (2012M) Capacitor)
pins: 1, 2

## NL0805B184K500CEDN
designator C?  Capacitance: 180nF  (hidden comment: *)
Capacitor, Ceramic (MLCC), 180nF, ±10%, 50V, X7R, ±10%, SMD 0805; Manufacturer: HUI JU; Manufacturer Part Number: NL0805B184K500CEDN
footprint CAP-0805 (0805 (2012M) Capacitor)
pins: 1, 2

## NL0805B472K500CPBN
designator C?  Capacitance: 4.7nF  (hidden comment: *)
Capacitor, Ceramic (MLCC), 4.7nF, ±10%, 50V, X7R, ±10%, SMD 0805; Manufacturer: HUI JU; Manufacturer Part Number: NL0805B472K500CPBN
footprint CAP-0805 (0805 (2012M) Capacitor)
pins: 1, 2

## NM0805B102K251CPBN
designator C?  Capacitance: 1nF  (hidden comment: *)
Capacitor, Ceramic (MLCC), 1nF, ±10%, 250V, X7R, ±10%, SMD 0805; Manufacturer: HUI JU; Manufacturer Part Number: NM0805B102K251CPBN
footprint CAP-0805 (0805 (2012M) Capacitor)
pins: 1, 2

## NM0805B102K501CPBN
designator C?  Capacitance: 1nF  (hidden comment: *)
Capacitor, Ceramic (MLCC), 1nF, ±10%, 500V, X7R, ±10%, SMD 0805; Manufacturer: HUI JU; Manufacturer Part Number: NM0805B102K501CPBN
footprint CAP-0805 (0805 (2012M) Capacitor)
pins: 1, 2

## NM0805B103K251CEDN
designator C?  Capacitance: 10nF  (hidden comment: *)
Capacitor, Ceramic (MLCC), 10nF, ±10%, 250V, X7R, ±10%, SMD 0805; Manufacturer: HUI JU; Manufacturer Part Number: NM0805B103K251CEDN
footprint CAP-0805 (0805 (2012M) Capacitor)
pins: 1, 2

## NM0805B103K501CEDN
designator C?  Capacitance: 10nF  (hidden comment: *)
Capacitor, Ceramic (MLCC), 10nF, ±10%, 500V, X7R, ±10%, SMD 0805; Manufacturer: HUI JU; Manufacturer Part Number: NM0805B103K501CEDN
footprint CAP-0805 (0805 (2012M) Capacitor)
pins: 1, 2

## NM0805B103K631CEDN
designator C?  Capacitance: 10nF  (hidden comment: *)
Capacitor, Ceramic (MLCC), 10nF, ±10%, 630V, X7R, ±10%, SMD 0805; Manufacturer: HUI JU; Manufacturer Part Number: NM0805B103K631CEDN
footprint CAP-0805 (0805 (2012M) Capacitor)
pins: 1, 2

## NM0805B104K101CEDN
designator C?  Capacitance: 100nF  (hidden comment: *)
Capacitor, Ceramic (MLCC), 100nF, ±10%, 100V, X7R, ±10%, SMD 0805; Manufacturer: HUI JU; Manufacturer Part Number: NM0805B104K101CEDN
footprint CAP-0805 (0805 (2012M) Capacitor)
pins: 1, 2

## NM0805B104K251CEDN
designator C?  Capacitance: 100nF  (hidden comment: *)
Capacitor, Ceramic (MLCC), 100nF, ±10%, 250V, X7R, ±10%, SMD 0805; Manufacturer: HUI JU; Manufacturer Part Number: NM0805B104K251CEDN
footprint CAP-0805 (0805 (2012M) Capacitor)
pins: 1, 2

## NM0805B104M101CEDN
designator C?  Capacitance: 100nF  (hidden comment: *)
Capacitor, Ceramic (MLCC), 100nF, ±20%, 100V, X7R, ±20%, SMD 0805; Manufacturer: HUI JU; Manufacturer Part Number: NM0805B104M101CEDN
footprint CAP-0805 (0805 (2012M) Capacitor)
pins: 1, 2

## NM0805B222K251CPBN
designator C?  Capacitance: 2.2nF  (hidden comment: *)
Capacitor, Ceramic (MLCC), 2.2nF, ±10%, 250V, X7R, ±10%, SMD 0805; Manufacturer: HUI JU; Manufacturer Part Number: NM0805B222K251CPBN
footprint CAP-0805 (0805 (2012M) Capacitor)
pins: 1, 2

## NM0805B223K101CPBN
designator C?  Capacitance: 22nF  (hidden comment: *)
Capacitor, Ceramic (MLCC), 22nF, ±10%, 100V, X7R, ±10%, SMD 0805; Manufacturer: HUI JU; Manufacturer Part Number: NM0805B223K101CPBN
footprint CAP-0805 (0805 (2012M) Capacitor)
pins: 1, 2

## NM0805B223K251CEDN
designator C?  Capacitance: 22nF  (hidden comment: *)
Capacitor, Ceramic (MLCC), 22nF, ±10%, 250V, X7R, ±10%, SMD 0805; Manufacturer: HUI JU; Manufacturer Part Number: NM0805B223K251CEDN
footprint CAP-0805 (0805 (2012M) Capacitor)
pins: 1, 2

## NM0805B224K101CEDN
designator C?  Capacitance: 220nF  (hidden comment: *)
Capacitor, Ceramic (MLCC), 220nF, ±10%, 100V, X7R, ±10%, SMD 0805; Manufacturer: HUI JU; Manufacturer Part Number: NM0805B224K101CEDN
footprint CAP-0805 (0805 (2012M) Capacitor)
pins: 1, 2

## NM0805B334K101CEDN
designator C?  Capacitance: 330nF  (hidden comment: *)
Capacitor, Ceramic (MLCC), 330nF, ±10%, 100V, X7R, ±10%, SMD 0805; Manufacturer: HUI JU; Manufacturer Part Number: NM0805B334K101CEDN
footprint CAP-0805 (0805 (2012M) Capacitor)
pins: 1, 2

## NM0805B471K101CPBN
designator C?  Capacitance: 470pF  (hidden comment: *)
Capacitor, Ceramic (MLCC), 470pF, ±10%, 100V, X7R, ±10%, SMD 0805; Manufacturer: HUI JU; Manufacturer Part Number: NM0805B471K101CPBN
footprint CAP-0805 (0805 (2012M) Capacitor)
pins: 1, 2

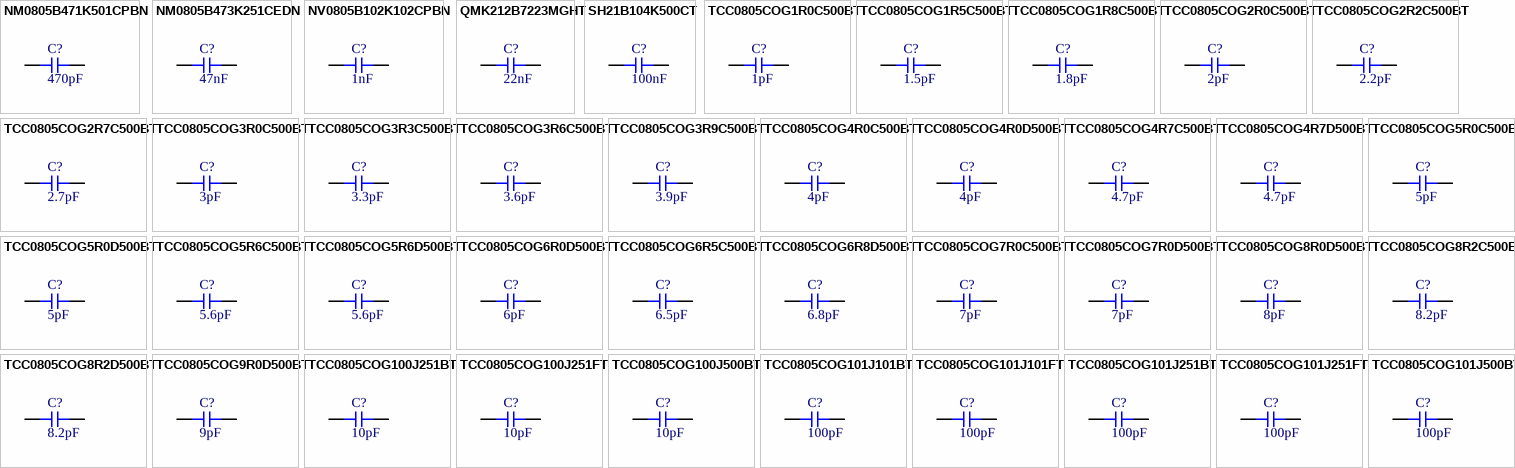
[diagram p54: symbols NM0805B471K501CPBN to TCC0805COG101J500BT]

## NM0805B471K501CPBN
designator C?  Capacitance: 470pF  (hidden comment: *)
Capacitor, Ceramic (MLCC), 470pF, ±10%, 500V, X7R, ±10%, SMD 0805; Manufacturer: HUI JU; Manufacturer Part Number: NM0805B471K501CPBN
footprint CAP-0805 (0805 (2012M) Capacitor)
pins: 1, 2

## NM0805B473K251CEDN
designator C?  Capacitance: 47nF  (hidden comment: *)
Capacitor, Ceramic (MLCC), 47nF, ±10%, 250V, X7R, ±10%, SMD 0805; Manufacturer: HUI JU; Manufacturer Part Number: NM0805B473K251CEDN
footprint CAP-0805 (0805 (2012M) Capacitor)
pins: 1, 2

## NV0805B102K102CPBN
designator C?  Capacitance: 1nF  (hidden comment: *)
Capacitor, Ceramic (MLCC), 1nF, ±10%, 1kV, X7R, ±10%, SMD 0805; Manufacturer: HUI JU; Manufacturer Part Number: NV0805B102K102CPBN
footprint CAP-0805 (0805 (2012M) Capacitor)
pins: 1, 2

## QMK212B7223MGHT
designator C?  Capacitance: 22nF  (hidden comment: *)
Capacitor, Ceramic (MLCC), 22nF, ±20%, 250V, X7R, ±20%, SMD 0805; Manufacturer: Taiyo Yuden; Manufacturer Part Number: QMK212B7223MGHT
footprint CAP-0805 (0805 (2012M) Capacitor)
pins: 1, 2

## SH21B104K500CT
designator C?  Capacitance: 100nF  (hidden comment: *)
Capacitor, Ceramic (MLCC), 100nF, ±10%, 50V, X7R, ±10%, SMD 0805; Manufacturer: Walsin Tech Corp; Manufacturer Part Number: SH21B104K500CT
footprint CAP-0805 (0805 (2012M) Capacitor)
pins: 1, 2

## TCC0805COG1R0C500BT
designator C?  Capacitance: 1pF  (hidden comment: *)
Capacitor, Ceramic (MLCC), 1pF, ±0.25pF, 50V, C0G, ±0.25pF, SMD 0805; Manufacturer: CCTC; Manufacturer Part Number: TCC0805COG1R0C500BT
footprint CAP-0805 (0805 (2012M) Capacitor)
pins: 1, 2

## TCC0805COG1R5C500BT
designator C?  Capacitance: 1.5pF  (hidden comment: *)
Capacitor, Ceramic (MLCC), 1.5pF, ±0.25pF, 50V, C0G, ±0.25pF, SMD 0805; Manufacturer: CCTC; Manufacturer Part Number: TCC0805COG1R5C500BT
footprint CAP-0805 (0805 (2012M) Capacitor)
pins: 1, 2

## TCC0805COG1R8C500BT
designator C?  Capacitance: 1.8pF  (hidden comment: *)
Capacitor, Ceramic (MLCC), 1.8pF, ±0.25pF, 50V, C0G, ±0.25pF, SMD 0805; Manufacturer: CCTC; Manufacturer Part Number: TCC0805COG1R8C500BT
footprint CAP-0805 (0805 (2012M) Capacitor)
pins: 1, 2

## TCC0805COG2R0C500BT
designator C?  Capacitance: 2pF  (hidden comment: *)
Capacitor, Ceramic (MLCC), 2pF, ±0.25pF, 50V, C0G, ±0.25pF, SMD 0805; Manufacturer: CCTC; Manufacturer Part Number: TCC0805COG2R0C500BT
footprint CAP-0805 (0805 (2012M) Capacitor)
pins: 1, 2

## TCC0805COG2R2C500BT
designator C?  Capacitance: 2.2pF  (hidden comment: *)
Capacitor, Ceramic (MLCC), 2.2pF, ±0.25pF, 50V, C0G, ±0.25pF, SMD 0805; Manufacturer: CCTC; Manufacturer Part Number: TCC0805COG2R2C500BT
footprint CAP-0805 (0805 (2012M) Capacitor)
pins: 1, 2

## TCC0805COG2R7C500BT
designator C?  Capacitance: 2.7pF  (hidden comment: *)
Capacitor, Ceramic (MLCC), 2.7pF, ±0.25pF, 50V, C0G, ±0.25pF, SMD 0805; Manufacturer: CCTC; Manufacturer Part Number: TCC0805COG2R7C500BT
footprint CAP-0805 (0805 (2012M) Capacitor)
pins: 1, 2

## TCC0805COG3R0C500BT
designator C?  Capacitance: 3pF  (hidden comment: *)
Capacitor, Ceramic (MLCC), 3pF, ±0.25pF, 50V, C0G, ±0.25pF, SMD 0805; Manufacturer: CCTC; Manufacturer Part Number: TCC0805COG3R0C500BT
footprint CAP-0805 (0805 (2012M) Capacitor)
pins: 1, 2

## TCC0805COG3R3C500BT
designator C?  Capacitance: 3.3pF  (hidden comment: *)
Capacitor, Ceramic (MLCC), 3.3pF, ±0.25pF, 50V, C0G, ±0.25pF, SMD 0805; Manufacturer: CCTC; Manufacturer Part Number: TCC0805COG3R3C500BT
footprint CAP-0805 (0805 (2012M) Capacitor)
pins: 1, 2

## TCC0805COG3R6C500BT
designator C?  Capacitance: 3.6pF  (hidden comment: *)
Capacitor, Ceramic (MLCC), 3.6pF, ±0.25pF, 50V, C0G, ±0.25pF, SMD 0805; Manufacturer: CCTC; Manufacturer Part Number: TCC0805COG3R6C500BT
footprint CAP-0805 (0805 (2012M) Capacitor)
pins: 1, 2

## TCC0805COG3R9C500BT
designator C?  Capacitance: 3.9pF  (hidden comment: *)
Capacitor, Ceramic (MLCC), 3.9pF, ±0.25pF, 50V, C0G, ±0.25pF, SMD 0805; Manufacturer: CCTC; Manufacturer Part Number: TCC0805COG3R9C500BT
footprint CAP-0805 (0805 (2012M) Capacitor)
pins: 1, 2

## TCC0805COG4R0C500BT
designator C?  Capacitance: 4pF  (hidden comment: *)
Capacitor, Ceramic (MLCC), 4pF, ±0.25pF, 50V, C0G, ±0.25pF, SMD 0805; Manufacturer: CCTC; Manufacturer Part Number: TCC0805COG4R0C500BT
footprint CAP-0805 (0805 (2012M) Capacitor)
pins: 1, 2

## TCC0805COG4R0D500BT
designator C?  Capacitance: 4pF  (hidden comment: *)
Capacitor, Ceramic (MLCC), 4pF, ±0.5pF, 50V, C0G, ±0.5pF, SMD 0805; Manufacturer: CCTC; Manufacturer Part Number: TCC0805COG4R0D500BT
footprint CAP-0805 (0805 (2012M) Capacitor)
pins: 1, 2

## TCC0805COG4R7C500BT
designator C?  Capacitance: 4.7pF  (hidden comment: *)
Capacitor, Ceramic (MLCC), 4.7pF, ±0.25pF, 50V, C0G, ±0.25pF, SMD 0805; Manufacturer: CCTC; Manufacturer Part Number: TCC0805COG4R7C500BT
footprint CAP-0805 (0805 (2012M) Capacitor)
pins: 1, 2

## TCC0805COG4R7D500BT
designator C?  Capacitance: 4.7pF  (hidden comment: *)
Capacitor, Ceramic (MLCC), 4.7pF, ±0.5pF, 50V, C0G, ±0.5pF, SMD 0805; Manufacturer: CCTC; Manufacturer Part Number: TCC0805COG4R7D500BT
footprint CAP-0805 (0805 (2012M) Capacitor)
pins: 1, 2

## TCC0805COG5R0C500BT
designator C?  Capacitance: 5pF  (hidden comment: *)
Capacitor, Ceramic (MLCC), 5pF, ±0.25pF, 50V, C0G, ±0.25pF, SMD 0805; Manufacturer: CCTC; Manufacturer Part Number: TCC0805COG5R0C500BT
footprint CAP-0805 (0805 (2012M) Capacitor)
pins: 1, 2

## TCC0805COG5R0D500BT
designator C?  Capacitance: 5pF  (hidden comment: *)
Capacitor, Ceramic (MLCC), 5pF, ±0.5pF, 50V, C0G, ±0.5pF, SMD 0805; Manufacturer: CCTC; Manufacturer Part Number: TCC0805COG5R0D500BT
footprint CAP-0805 (0805 (2012M) Capacitor)
pins: 1, 2

## TCC0805COG5R6C500BT
designator C?  Capacitance: 5.6pF  (hidden comment: *)
Capacitor, Ceramic (MLCC), 5.6pF, ±0.25pF, 50V, C0G, ±0.25pF, SMD 0805; Manufacturer: CCTC; Manufacturer Part Number: TCC0805COG5R6C500BT
footprint CAP-0805 (0805 (2012M) Capacitor)
pins: 1, 2

## TCC0805COG5R6D500BT
designator C?  Capacitance: 5.6pF  (hidden comment: *)
Capacitor, Ceramic (MLCC), 5.6pF, ±0.5pF, 50V, C0G, ±0.5pF, SMD 0805; Manufacturer: CCTC; Manufacturer Part Number: TCC0805COG5R6D500BT
footprint CAP-0805 (0805 (2012M) Capacitor)
pins: 1, 2

## TCC0805COG6R0D500BT
designator C?  Capacitance: 6pF  (hidden comment: *)
Capacitor, Ceramic (MLCC), 6pF, ±0.5pF, 50V, C0G, ±0.5pF, SMD 0805; Manufacturer: CCTC; Manufacturer Part Number: TCC0805COG6R0D500BT
footprint CAP-0805 (0805 (2012M) Capacitor)
pins: 1, 2

## TCC0805COG6R5C500BT
designator C?  Capacitance: 6.5pF  (hidden comment: *)
Capacitor, Ceramic (MLCC), 6.5pF, ±0.25pF, 50V, C0G, ±0.25pF, SMD 0805; Manufacturer: CCTC; Manufacturer Part Number: TCC0805COG6R5C500BT
footprint CAP-0805 (0805 (2012M) Capacitor)
pins: 1, 2

## TCC0805COG6R8D500BT
designator C?  Capacitance: 6.8pF  (hidden comment: *)
Capacitor, Ceramic (MLCC), 6.8pF, ±0.5pF, 50V, C0G, ±0.5pF, SMD 0805; Manufacturer: CCTC; Manufacturer Part Number: TCC0805COG6R8D500BT
footprint CAP-0805 (0805 (2012M) Capacitor)
pins: 1, 2

## TCC0805COG7R0C500BT
designator C?  Capacitance: 7pF  (hidden comment: *)
Capacitor, Ceramic (MLCC), 7pF, ±0.25pF, 50V, C0G, ±0.25pF, SMD 0805; Manufacturer: CCTC; Manufacturer Part Number: TCC0805COG7R0C500BT
footprint CAP-0805 (0805 (2012M) Capacitor)
pins: 1, 2

## TCC0805COG7R0D500BT
designator C?  Capacitance: 7pF  (hidden comment: *)
Capacitor, Ceramic (MLCC), 7pF, ±0.5pF, 50V, C0G, ±0.5pF, SMD 0805; Manufacturer: CCTC; Manufacturer Part Number: TCC0805COG7R0D500BT
footprint CAP-0805 (0805 (2012M) Capacitor)
pins: 1, 2

## TCC0805COG8R0D500BT
designator C?  Capacitance: 8pF  (hidden comment: *)
Capacitor, Ceramic (MLCC), 8pF, ±0.5pF, 50V, C0G, ±0.5pF, SMD 0805; Manufacturer: CCTC; Manufacturer Part Number: TCC0805COG8R0D500BT
footprint CAP-0805 (0805 (2012M) Capacitor)
pins: 1, 2

## TCC0805COG8R2C500BT
designator C?  Capacitance: 8.2pF  (hidden comment: *)
Capacitor, Ceramic (MLCC), 8.2pF, ±0.25pF, 50V, C0G, ±0.25pF, SMD 0805; Manufacturer: CCTC; Manufacturer Part Number: TCC0805COG8R2C500BT
footprint CAP-0805 (0805 (2012M) Capacitor)
pins: 1, 2

## TCC0805COG8R2D500BT
designator C?  Capacitance: 8.2pF  (hidden comment: *)
Capacitor, Ceramic (MLCC), 8.2pF, ±0.5pF, 50V, C0G, ±0.5pF, SMD 0805; Manufacturer: CCTC; Manufacturer Part Number: TCC0805COG8R2D500BT
footprint CAP-0805 (0805 (2012M) Capacitor)
pins: 1, 2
